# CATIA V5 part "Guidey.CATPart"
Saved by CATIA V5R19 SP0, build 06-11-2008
Part number: Guidey
Publications: "L", "H", "P", "e"
Bounding box of the stored display mesh (mm): x -100 to 100, y 0 to 50, z 0 to 100
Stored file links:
  G:\EU_thinkMotion\CFAO_2010\MMS_groupe3\MMS_groupe3\A reprendre\evulliez\evulliez\Guidey.CATPart
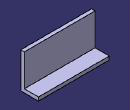
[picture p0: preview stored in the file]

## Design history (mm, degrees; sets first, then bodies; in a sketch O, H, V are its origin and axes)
Parameters
  L = 200 mm
  H = 100 mm
  P = 50 mm
  e = 10 mm
Body1 (main body)
  Sketch1 on yz-plane, origin (0, 0, 0), H (0, 1, 0), V (0, 0, 1)
    line L1 (0, 0) -> (50, 0)
    line L2 (0, 0) -> (0, 100)
    line L3 (50, 0) -> (50, 10)
    line L4 (0, 100) -> (10, 100)
    line L5 (50, 10) -> (10, 10)
    line L6 (10, 100) -> (10, 10)
    length L1 = 50 {= P}
    length L3 = 10 {= e}
    length L2 = 100 {= H}
    length L4 = 10 {= e}
    horizontal: L1 H, L4 H, L5 H
    vertical: L2 V, L3 V, L6 V
  Pad1: profile Sketch1, direction (1, 0, 0), length 100 {= L /2}, mirrored extent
